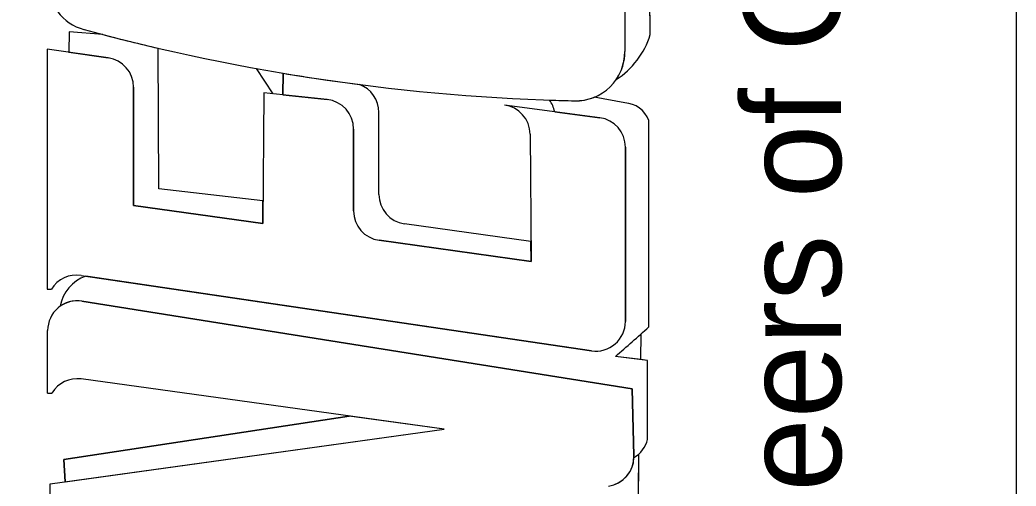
# Model space of a CAD drawing. Extents: x 1485751 to 1485785, y 230696.6 to 230718.6.
# Drawn here: x 1485783.769 to 1485784.533, y 230715.175 to 230715.532 of the extents above; entities that cross this region are included whole.
import ezdxf

# ---------------------------------------------------------------- set-up
doc = ezdxf.new("R2010")
doc.units = 0
doc.layers.add('SH_Border', color=7, linetype='Continuous')

msp = doc.modelspace()

# ---------------------------------------------------------------- linework, layer by layer
at = {"layer": 'SH_Border'}
for p, q in [((1485784.25235, 230715.52061), (1485784.25132, 230715.64075)), ((1485784.25235, 230715.52061), (1485784.25132, 230715.64075)), ((1485784.25235, 230715.52061), (1485784.25132, 230715.64075)), ((1485784.23301, 230715.61233), (1485784.23301, 230715.5077)), ((1485784.23301, 230715.61233), (1485784.23301, 230715.5077)), ((1485784.23301, 230715.61233), (1485784.23301, 230715.5077)), ((1485783.80699, 230715.52266), (1485783.80683, 230715.50714)), ((1485783.80699, 230715.52266), (1485783.80683, 230715.50714)), ((1485783.80699, 230715.52266), (1485783.80683, 230715.50714)), ((1485783.83291, 230715.52058), (1485783.80699, 230715.52266)), ((1485783.83291, 230715.52058), (1485783.80699, 230715.52266)), ((1485783.83291, 230715.52058), (1485783.80699, 230715.52266)), ((1485783.83689, 230715.50284), (1485783.79009, 230715.50953)), ((1485783.79009, 230715.50953), (1485783.79009, 230715.32551)), ((1485783.83689, 230715.50284), (1485783.79009, 230715.50953)), ((1485783.79009, 230715.50953), (1485783.79009, 230715.32551)), ((1485783.83689, 230715.50284), (1485783.79009, 230715.50953)), ((1485783.79009, 230715.50953), (1485783.79009, 230715.32551)), ((1485783.87574, 230715.40252), (1485783.87515, 230715.51016)), ((1485783.87574, 230715.40252), (1485783.87515, 230715.51016)), ((1485783.87574, 230715.40252), (1485783.87515, 230715.51016)), ((1485783.96336, 230715.47519), (1485783.95069, 230715.49456)), ((1485783.96336, 230715.47519), (1485783.95069, 230715.49456)), ((1485783.96336, 230715.47519), (1485783.95069, 230715.49456)), ((1485783.97073, 230715.47442), (1485783.97099, 230715.49103)), ((1485783.97073, 230715.47442), (1485783.97099, 230715.49103)), ((1485783.97073, 230715.47442), (1485783.97099, 230715.49103)), ((1485783.85637, 230715.38981), (1485783.85637, 230715.48038)), ((1485783.85637, 230715.38981), (1485783.85637, 230715.48038)), ((1485783.85637, 230715.38981), (1485783.85637, 230715.48038)), ((1485783.95622, 230715.47594), (1485783.95536, 230715.37602)), ((1485783.95622, 230715.47594), (1485783.95536, 230715.37602)), ((1485783.95622, 230715.47594), (1485783.95536, 230715.37602)), ((1485784.00475, 230715.47087), (1485783.95622, 230715.47594)), ((1485784.00475, 230715.47087), (1485783.95622, 230715.47594)), ((1485784.00475, 230715.47087), (1485783.95622, 230715.47594)), ((1485784.23285, 230715.46824), (1485784.20934, 230715.47262)), ((1485784.23285, 230715.46824), (1485784.20934, 230715.47262)), ((1485784.23285, 230715.46824), (1485784.20934, 230715.47262)), ((1485784.2137, 230715.45692), (1485784.14059, 230715.46667)), ((1485784.2137, 230715.45692), (1485784.14059, 230715.46667)), ((1485784.2137, 230715.45692), (1485784.14059, 230715.46667)), ((1485784.04446, 230715.39822), (1485784.04446, 230715.46102)), ((1485784.04446, 230715.39822), (1485784.04446, 230715.46102)), ((1485784.04446, 230715.39822), (1485784.04446, 230715.46102)), ((1485784.02508, 230715.38551), (1485784.02508, 230715.4483)), ((1485784.02508, 230715.38551), (1485784.02508, 230715.4483)), ((1485784.02508, 230715.38551), (1485784.02508, 230715.4483)), ((1485784.25132, 230715.29676), (1485784.25132, 230715.45489)), ((1485784.25132, 230715.29676), (1485784.25132, 230715.45489)), ((1485784.25132, 230715.29676), (1485784.25132, 230715.45489)), ((1485784.16028, 230715.44437), (1485784.16109, 230715.34674)), ((1485784.16028, 230715.44437), (1485784.16109, 230715.34674)), ((1485784.16028, 230715.44437), (1485784.16109, 230715.34674)), ((1485784.23339, 230715.30084), (1485784.23339, 230715.43443)), ((1485784.23339, 230715.30084), (1485784.23339, 230715.43443)), ((1485784.23339, 230715.30084), (1485784.23339, 230715.43443)), ((1485783.95551, 230715.39327), (1485783.87574, 230715.40252)), ((1485783.95551, 230715.39327), (1485783.87574, 230715.40252)), ((1485783.95551, 230715.39327), (1485783.87574, 230715.40252)), ((1485783.95536, 230715.37602), (1485783.85637, 230715.38981)), ((1485783.95536, 230715.37602), (1485783.85637, 230715.38981)), ((1485783.95536, 230715.37602), (1485783.85637, 230715.38981)), ((1485784.16096, 230715.36218), (1485784.064, 230715.37575)), ((1485784.16096, 230715.36218), (1485784.064, 230715.37575)), ((1485784.16096, 230715.36218), (1485784.064, 230715.37575)), ((1485784.16109, 230715.34674), (1485784.04463, 230715.36304)), ((1485784.16109, 230715.34674), (1485784.04463, 230715.36304)), ((1485784.16109, 230715.34674), (1485784.04463, 230715.36304)), ((1485783.81609, 230715.33622), (1485784.20739, 230715.2784)), ((1485783.81609, 230715.33622), (1485784.20739, 230715.2784)), ((1485783.81609, 230715.33622), (1485784.20739, 230715.2784)), ((1485783.79009, 230715.32551), (1485783.79336, 230715.32551)), ((1485783.79009, 230715.32551), (1485783.79336, 230715.32551)), ((1485783.79009, 230715.32551), (1485783.79336, 230715.32551)), ((1485784.23859, 230715.24939), (1485783.81676, 230715.31644)), ((1485784.23859, 230715.24939), (1485783.81676, 230715.31644)), ((1485784.23859, 230715.24939), (1485783.81676, 230715.31644)), ((1485783.79051, 230715.2461), (1485783.79051, 230715.29404)), ((1485783.79051, 230715.2461), (1485783.79051, 230715.29404)), ((1485783.79051, 230715.2461), (1485783.79051, 230715.29404)), ((1485784.2451, 230715.27174), (1485784.24545, 230715.29141)), ((1485784.2451, 230715.27174), (1485784.24545, 230715.29141)), ((1485784.2451, 230715.27174), (1485784.24545, 230715.29141)), ((1485784.2503, 230715.27109), (1485784.22567, 230715.27417)), ((1485784.2503, 230715.27109), (1485784.22567, 230715.27417)), ((1485784.2503, 230715.27109), (1485784.22567, 230715.27417)), ((1485784.2503, 230715.2105), (1485784.2503, 230715.27109)), ((1485784.2503, 230715.2105), (1485784.2503, 230715.27109)), ((1485784.2503, 230715.2105), (1485784.2503, 230715.27109)), ((1485784.09452, 230715.21839), (1485783.8163, 230715.25684)), ((1485784.09452, 230715.21839), (1485783.8163, 230715.25684)), ((1485784.09452, 230715.21839), (1485783.8163, 230715.25684)), ((1485784.23995, 230715.19789), (1485784.23859, 230715.24939)), ((1485784.23995, 230715.19789), (1485784.23859, 230715.24939)), ((1485784.23995, 230715.19789), (1485784.23859, 230715.24939)), ((1485783.79051, 230715.2461), (1485783.79378, 230715.2461)), ((1485783.79051, 230715.2461), (1485783.79378, 230715.2461)), ((1485783.79051, 230715.2461), (1485783.79378, 230715.2461)), ((1485783.80289, 230715.1951), (1485784.02153, 230715.22848)), ((1485783.80289, 230715.1951), (1485784.02153, 230715.22848)), ((1485783.80289, 230715.1951), (1485784.02153, 230715.22848)), ((1485783.79244, 230715.17654), (1485784.09452, 230715.21839)), ((1485783.79244, 230715.17654), (1485784.09452, 230715.21839)), ((1485783.79244, 230715.17654), (1485784.09452, 230715.21839)), ((1485784.24304, 230715.11402), (1485784.24376, 230715.19938)), ((1485784.24304, 230715.11402), (1485784.24376, 230715.19938)), ((1485784.24304, 230715.11402), (1485784.24376, 230715.19938)), ((1485783.80385, 230715.17812), (1485783.80289, 230715.1951)), ((1485783.80385, 230715.17812), (1485783.80289, 230715.1951)), ((1485783.80385, 230715.17812), (1485783.80289, 230715.1951)), ((1485783.79244, 230715.11608), (1485783.79244, 230715.17654)), ((1485783.79244, 230715.11608), (1485783.79244, 230715.17654)), ((1485783.79244, 230715.11608), (1485783.79244, 230715.17654))]:
    msp.add_line(p, q, dxfattribs=at)
msp.add_lwpolyline([(1485753.03285, 230718.14083), (1485784.53285, 230718.14083), (1485784.53285, 230697.14083), (1485753.03285, 230697.14083)], close=True, dxfattribs=at)
for points in [[(1485784.25235, 230715.52061), (1485784.25132, 230715.64075)], [(1485784.25235, 230715.52061), (1485784.25132, 230715.64075)], [(1485784.25235, 230715.52061), (1485784.25132, 230715.64075)], [(1485784.23301, 230715.61233), (1485784.23301, 230715.5077)], [(1485784.23301, 230715.61233), (1485784.23301, 230715.5077)], [(1485784.23301, 230715.61233), (1485784.23301, 230715.5077)], [(1485783.83291, 230715.52058), (1485783.80699, 230715.52266), (1485783.80683, 230715.50714), (1485783.83689, 230715.50284)], [(1485783.83291, 230715.52058), (1485783.80699, 230715.52266), (1485783.80683, 230715.50714), (1485783.83689, 230715.50284)], [(1485783.83291, 230715.52058), (1485783.80699, 230715.52266), (1485783.80683, 230715.50714), (1485783.83689, 230715.50284)], [(1485783.85637, 230715.48038), (1485783.85637, 230715.38981), (1485783.95536, 230715.37602), (1485783.95551, 230715.39327), (1485783.87574, 230715.40252), (1485783.87515, 230715.51016)], [(1485783.85637, 230715.48038), (1485783.85637, 230715.38981), (1485783.95536, 230715.37602), (1485783.95551, 230715.39327), (1485783.87574, 230715.40252), (1485783.87515, 230715.51016)], [(1485783.85637, 230715.48038), (1485783.85637, 230715.38981), (1485783.95536, 230715.37602), (1485783.95551, 230715.39327), (1485783.87574, 230715.40252), (1485783.87515, 230715.51016)], [(1485783.97099, 230715.49103), (1485783.97073, 230715.47442), (1485784.00475, 230715.47087)], [(1485783.97099, 230715.49103), (1485783.97073, 230715.47442), (1485784.00475, 230715.47087)], [(1485783.97099, 230715.49103), (1485783.97073, 230715.47442), (1485784.00475, 230715.47087)], [(1485784.23285, 230715.46824), (1485784.20934, 230715.47262)], [(1485784.23285, 230715.46824), (1485784.20934, 230715.47262)], [(1485784.23285, 230715.46824), (1485784.20934, 230715.47262)], [(1485784.04446, 230715.39822), (1485784.04446, 230715.46102)], [(1485784.04446, 230715.39822), (1485784.04446, 230715.46102)], [(1485784.04446, 230715.39822), (1485784.04446, 230715.46102)], [(1485784.17918, 230715.46152), (1485784.2137, 230715.45692)], [(1485784.17918, 230715.46152), (1485784.2137, 230715.45692)], [(1485784.17918, 230715.46152), (1485784.2137, 230715.45692)], [(1485784.02508, 230715.4483), (1485784.02508, 230715.38551)], [(1485784.02508, 230715.4483), (1485784.02508, 230715.38551)], [(1485784.02508, 230715.4483), (1485784.02508, 230715.38551)], [(1485784.25132, 230715.29676), (1485784.25132, 230715.45489)], [(1485784.25132, 230715.29676), (1485784.25132, 230715.45489)], [(1485784.25132, 230715.29676), (1485784.25132, 230715.45489)], [(1485784.23339, 230715.43443), (1485784.23339, 230715.30084)], [(1485784.23339, 230715.43443), (1485784.23339, 230715.30084)], [(1485784.23339, 230715.43443), (1485784.23339, 230715.30084)], [(1485784.04463, 230715.36304), (1485784.16109, 230715.34674), (1485784.16096, 230715.36218), (1485784.064, 230715.37575)], [(1485784.04463, 230715.36304), (1485784.16109, 230715.34674), (1485784.16096, 230715.36218), (1485784.064, 230715.37575)], [(1485784.04463, 230715.36304), (1485784.16109, 230715.34674), (1485784.16096, 230715.36218), (1485784.064, 230715.37575)], [(1485784.20739, 230715.2784), (1485783.81978, 230715.33567)], [(1485784.20739, 230715.2784), (1485783.81978, 230715.33567)], [(1485784.20739, 230715.2784), (1485783.81978, 230715.33567)], [(1485783.81676, 230715.31644), (1485784.23859, 230715.24939), (1485784.23995, 230715.19789)], [(1485783.81676, 230715.31644), (1485784.23859, 230715.24939), (1485784.23995, 230715.19789)], [(1485783.81676, 230715.31644), (1485784.23859, 230715.24939), (1485784.23995, 230715.19789)], [(1485784.2503, 230715.2105), (1485784.2503, 230715.27109), (1485784.2451, 230715.27174), (1485784.22567, 230715.27417)], [(1485784.2503, 230715.2105), (1485784.2503, 230715.27109), (1485784.2451, 230715.27174), (1485784.22567, 230715.27417)], [(1485784.2503, 230715.2105), (1485784.2503, 230715.27109), (1485784.2451, 230715.27174), (1485784.22567, 230715.27417)], [(1485783.80385, 230715.17812), (1485784.09452, 230715.21839), (1485784.02153, 230715.22848), (1485783.80289, 230715.1951), (1485783.80385, 230715.17812)], [(1485783.80385, 230715.17812), (1485784.09452, 230715.21839), (1485784.02153, 230715.22848), (1485783.80289, 230715.1951), (1485783.80385, 230715.17812)], [(1485783.80385, 230715.17812), (1485784.09452, 230715.21839), (1485784.02153, 230715.22848), (1485783.80289, 230715.1951), (1485783.80385, 230715.17812)], [(1485784.15842, 230715.16607), (1485784.18677, 230715.12362), (1485784.24304, 230715.11402), (1485784.24376, 230715.19938)], [(1485784.15842, 230715.16607), (1485784.18677, 230715.12362), (1485784.24304, 230715.11402), (1485784.24376, 230715.19938)], [(1485784.15842, 230715.16607), (1485784.18677, 230715.12362), (1485784.24304, 230715.11402), (1485784.24376, 230715.19938)]]:
    msp.add_lwpolyline(points, dxfattribs=at)
for centre, radius, start, end in [((1485783.82829, 230715.56095), 0.03781, 180, 254.79162), ((1485783.82829, 230715.56095), 0.03781, 180, 254.79162), ((1485783.82829, 230715.56095), 0.03781, 180, 254.79162), ((1485784.23016, 230717.0392), 1.56971, 254.79162, 268.69253), ((1485784.23016, 230717.0392), 1.56971, 254.79162, 268.69253), ((1485784.23016, 230717.0392), 1.56971, 254.79162, 268.69253), ((1485784.23016, 230717.0392), 1.56971, 255.34062, 256.92894), ((1485784.23016, 230717.0392), 1.56971, 255.34062, 256.92894), ((1485784.23016, 230717.0392), 1.56971, 255.34062, 256.92894), ((1485784.19322, 230715.53826), 0.06171, 302.39655, 343.37547), ((1485784.19322, 230715.53826), 0.06171, 302.39655, 343.37547), ((1485784.19322, 230715.53826), 0.06171, 302.39655, 343.37547), ((1485784.19322, 230715.53826), 0.06171, 302.39655, 343.37547), ((1485784.19322, 230715.53826), 0.06171, 302.39655, 343.37547), ((1485784.19322, 230715.53826), 0.06171, 302.39655, 343.37547), ((1485783.83368, 230715.48038), 0.02269, 0, 81.86464), ((1485783.83368, 230715.48038), 0.02269, 0, 81.86464), ((1485783.83368, 230715.48038), 0.02269, 0, 81.86464), ((1485783.83368, 230715.48038), 0.02269, 0, 81.86464), ((1485783.83368, 230715.48038), 0.02269, 0, 81.86464), ((1485783.83368, 230715.48038), 0.02269, 0, 81.86464), ((1485784.1952, 230715.5077), 0.03781, 268.69253, 0), ((1485784.1952, 230715.5077), 0.03781, 268.69253, 0), ((1485784.1952, 230715.5077), 0.03781, 268.69253, 0), ((1485784.1952, 230715.5077), 0.03781, 325.27661, 0), ((1485784.1952, 230715.5077), 0.03781, 325.27661, 0), ((1485784.1952, 230715.5077), 0.03781, 325.27661, 0), ((1485784.23016, 230717.0392), 1.56971, 260.49664, 262.65334), ((1485784.23016, 230717.0392), 1.56971, 260.49664, 262.65334), ((1485784.23016, 230717.0392), 1.56971, 260.49664, 262.65334), ((1485784.02177, 230715.46102), 0.02269, 0, 70.25544), ((1485784.02177, 230715.46102), 0.02269, 0, 70.25544), ((1485784.02177, 230715.46102), 0.02269, 0, 70.25544), ((1485784.02177, 230715.46102), 0.02269, 0, 70.25544), ((1485784.02177, 230715.46102), 0.02269, 0, 70.25544), ((1485784.02177, 230715.46102), 0.02269, 0, 70.25544), ((1485784.00239, 230715.4483), 0.02269, 0, 84.03166), ((1485784.00239, 230715.4483), 0.02269, 0, 84.03166), ((1485784.00239, 230715.4483), 0.02269, 0, 84.03166), ((1485784.00239, 230715.4483), 0.02269, 0, 84.03166), ((1485784.00239, 230715.4483), 0.02269, 0, 84.03166), ((1485784.00239, 230715.4483), 0.02269, 0, 84.03166), ((1485784.15697, 230715.4569), 0.02269, 11.76029, 36.6658), ((1485784.23016, 230717.0392), 1.56971, 267.99237, 268.69253), ((1485784.15697, 230715.4569), 0.02269, 11.76029, 36.6658), ((1485784.15697, 230715.4569), 0.02269, 11.76029, 36.6658), ((1485784.23016, 230717.0392), 1.56971, 267.99237, 268.69253), ((1485784.15697, 230715.4569), 0.02269, 11.76029, 36.6658), ((1485784.15697, 230715.4569), 0.02269, 11.76029, 36.6658), ((1485784.23016, 230717.0392), 1.56971, 267.99237, 268.69253), ((1485784.15697, 230715.4569), 0.02269, 11.76029, 36.6658), ((1485784.1952, 230715.5077), 0.03781, 268.69253, 291.95024), ((1485784.1952, 230715.5077), 0.03781, 268.69253, 291.95024), ((1485784.1952, 230715.5077), 0.03781, 268.69253, 291.95024), ((1485784.13759, 230715.44418), 0.02269, 0.4732, 82.40046), ((1485784.13759, 230715.44418), 0.02269, 0.4732, 82.40046), ((1485784.13759, 230715.44418), 0.02269, 0.4732, 82.40046), ((1485784.23207, 230715.44771), 0.02055, 20.45964, 87.82957), ((1485784.23207, 230715.44771), 0.02055, 20.45964, 87.82957), ((1485784.23207, 230715.44771), 0.02055, 20.45964, 87.82957), ((1485784.23207, 230715.44771), 0.02055, 20.45964, 87.82957), ((1485784.23207, 230715.44771), 0.02055, 20.45964, 87.82957), ((1485784.23207, 230715.44771), 0.02055, 20.45964, 87.82957), ((1485784.2107, 230715.43443), 0.02269, 0, 82.40046), ((1485784.2107, 230715.43443), 0.02269, 0, 82.40046), ((1485784.2107, 230715.43443), 0.02269, 0, 82.40046), ((1485784.2107, 230715.43443), 0.02269, 0, 82.40046), ((1485784.2107, 230715.43443), 0.02269, 0, 82.40046), ((1485784.2107, 230715.43443), 0.02269, 0, 82.40046), ((1485784.06714, 230715.39822), 0.02269, 180, 262.03311), ((1485784.06714, 230715.39822), 0.02269, 180, 262.03311), ((1485784.06714, 230715.39822), 0.02269, 180, 262.03311), ((1485784.06714, 230715.39822), 0.02269, 180, 262.03311), ((1485784.06714, 230715.39822), 0.02269, 180, 262.03311), ((1485784.06714, 230715.39822), 0.02269, 180, 262.03311), ((1485784.04777, 230715.38551), 0.02269, 180, 262.03311), ((1485784.04777, 230715.38551), 0.02269, 180, 262.03311), ((1485784.04777, 230715.38551), 0.02269, 180, 262.03311), ((1485784.04777, 230715.38551), 0.02269, 180, 262.03311), ((1485784.04777, 230715.38551), 0.02269, 180, 262.03311), ((1485784.04777, 230715.38551), 0.02269, 180, 262.03311), ((1485783.81278, 230715.31378), 0.02269, 81.59392, 148.85913), ((1485783.81278, 230715.31378), 0.02269, 81.59392, 148.85913), ((1485783.81278, 230715.31378), 0.02269, 81.59392, 148.85913), ((1485783.82978, 230715.30715), 0.03022, 109.32309, 169.78308), ((1485783.82978, 230715.30715), 0.03022, 109.32309, 169.78308), ((1485783.82978, 230715.30715), 0.03022, 109.32309, 169.78308), ((1485783.82978, 230715.30715), 0.03022, 109.32309, 169.78308), ((1485783.82978, 230715.30715), 0.03022, 109.32309, 169.78308), ((1485783.82978, 230715.30715), 0.03022, 109.32309, 169.78308), ((1485783.8132, 230715.29404), 0.02269, 80.96848, 180), ((1485783.8132, 230715.29404), 0.02269, 80.96848, 180), ((1485783.8132, 230715.29404), 0.02269, 80.96848, 180), ((1485783.8132, 230715.29404), 0.02269, 80.96848, 125.47349), ((1485783.8132, 230715.29404), 0.02269, 80.96848, 125.47349), ((1485783.8132, 230715.29404), 0.02269, 80.96848, 125.47349), ((1485784.2107, 230715.30084), 0.02269, 261.59392, 0), ((1485784.2107, 230715.30084), 0.02269, 261.59392, 0), ((1485784.2107, 230715.30084), 0.02269, 261.59392, 0), ((1485784.2107, 230715.30084), 0.02269, 261.59392, 0), ((1485784.2107, 230715.30084), 0.02269, 261.59392, 0), ((1485784.2107, 230715.30084), 0.02269, 261.59392, 0), ((1485783.73286, 230715.85967), 0.7653, 310.08662, 312.64602), ((1485783.73286, 230715.85967), 0.7653, 310.08662, 312.64602), ((1485783.73286, 230715.85967), 0.7653, 310.08662, 312.64602), ((1485783.73286, 230715.85967), 0.7653, 310.08662, 312.64602), ((1485783.73286, 230715.85967), 0.7653, 310.08662, 312.64602), ((1485783.73286, 230715.85967), 0.7653, 310.08662, 312.64602), ((1485783.8132, 230715.23437), 0.02269, 82.13091, 148.85913), ((1485783.8132, 230715.23437), 0.02269, 82.13091, 148.85913), ((1485783.8132, 230715.23437), 0.02269, 82.13091, 148.85913), ((1485784.2297, 230715.21513), 0.02111, 299.03105, 347.33987), ((1485784.2297, 230715.21513), 0.02111, 299.03105, 347.33987), ((1485784.2297, 230715.21513), 0.02111, 299.03105, 347.33987), ((1485784.2297, 230715.21513), 0.02111, 299.03105, 347.33987), ((1485784.2297, 230715.21513), 0.02111, 299.03105, 347.33987), ((1485784.2297, 230715.21513), 0.02111, 299.03105, 347.33987), ((1485784.21727, 230715.19729), 0.02269, 278.04089, 1.50643), ((1485784.21727, 230715.19729), 0.02269, 278.04089, 1.50643), ((1485784.21727, 230715.19729), 0.02269, 278.04089, 1.50643), ((1485784.21727, 230715.19729), 0.02269, 278.04089, 358.43264), ((1485784.21727, 230715.19729), 0.02269, 278.04089, 358.43264), ((1485784.21727, 230715.19729), 0.02269, 278.04089, 358.43264), ((1485784.21727, 230715.19729), 0.02269, 358.43264, 1.50643), ((1485784.21727, 230715.19729), 0.02269, 358.43264, 1.50643), ((1485784.21727, 230715.19729), 0.02269, 358.43264, 1.50643)]:
    msp.add_arc(centre, radius, start, end, dxfattribs=at)

# ---------------------------------------------------------------- texts
msp.add_text('Engineers of Ohio, Inc.', height=0.075625, rotation=90, dxfattribs=at).set_placement((1485784.39868, 230714.91187))

doc.saveas('drawing.dxf')
